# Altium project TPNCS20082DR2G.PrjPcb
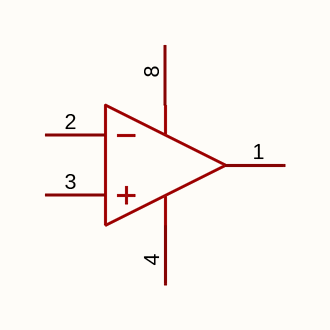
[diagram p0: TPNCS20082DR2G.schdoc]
1 sheet, 1 parts. Net scope: global (net labels, ports and power ports of the same name join across sheets).

## Sheet TPNCS20082DR2G.schdoc
size 127 x 101 mm

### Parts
U?  tpncs20082dr2g  [SOP-8_L4.9-W3.9-P1.27-LS6.0-BL]  (value not drawn)  (part A of 2)

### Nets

Not connected (* = marked no-connect by the designer): U? 1(OUT_A) 2(IN_A-) 3(IN_A+) 4(VSS) 8(VDD)

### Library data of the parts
U? = tpncs20082dr2g: 放大器数:2;轨到轨:轨到轨输入,轨到轨输出;增益带宽积(GBW):1MHz;输入失调电压(Vos):5mV;压摆率(SR):600V/ms;输入偏置电流(Ib):10pA;; Manufacturer: TECH PUBLIC(台舟); AddInBom: yes; ModelId: 75c24a7891ee4dd6bdac16a7163ff87e; ModelName: SOP-8_L4.9-W3.9-P1.27-LS6.0-BL-1; ModelTransform: 192.913,236.22,0,0,0,0,-0.393,2.749,0; Number of Channels: 2; Maximum Power Supply Range (Vdd-Vss): 7V; Gain Bandwidth Product: 1MHz; Vos - Input Offset Voltage: 5mV; Input Offset Voltage Drift(Vos TC): 2uV/℃; Ib - Input Bias Current: 10pA; Input Voltage Noise Density: 50nV/√Hz@1kHz; Common Mode Rejection Ratio(CMRR): 80dB; Quiescent Current: 55uA; Output Current: 20mA; Single supply: 1.8V~5.5V; Dual Supply: -2.75V~-900mV；900mV~2.75V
